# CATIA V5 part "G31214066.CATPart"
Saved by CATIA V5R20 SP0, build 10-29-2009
Part number: G31214066
Revision: 3
Definition: design
Nomenclature: G31214066
Source: made
Description: NOT SPECIFIED
Bounding box of the stored display mesh (mm): x -6 to 66, y -12.31 to 12.31, z -12.5 to 12.5
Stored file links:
  C:\Users\Raffaele\Desktop\3D X SITO CF\BOLEX\23-BUSH REF 312\G31214066.CATPart

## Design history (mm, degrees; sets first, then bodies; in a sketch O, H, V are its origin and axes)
Body1 "MANIFOLD_SOLID_BREP #14731" (main body)
  Solid1: solid without history
Body2 "MANIFOLD_SOLID_BREP #14874"
  Solid2: solid without history
Body3 "MANIFOLD_SOLID_BREP #15017"
  Solid3: solid without history
Body4 "MANIFOLD_SOLID_BREP #15160"
  Solid4: solid without history
Body5 "MANIFOLD_SOLID_BREP #15303"
  Solid5: solid without history
Body6 "MANIFOLD_SOLID_BREP #15448"
  Solid6: solid without history
Body7 "MANIFOLD_SOLID_BREP #15593"
  Solid7: solid without history
Body8 "MANIFOLD_SOLID_BREP #15738"
  Solid8: solid without history
Body9 "MANIFOLD_SOLID_BREP #15883"
  Solid9: solid without history
Body10 "MANIFOLD_SOLID_BREP #16028"
  Solid10: solid without history
Body11 "MANIFOLD_SOLID_BREP #16173"
  Solid11: solid without history
Body12 "MANIFOLD_SOLID_BREP #16318"
  Solid12: solid without history
Body13 "MANIFOLD_SOLID_BREP #16463"
  Solid13: solid without history
Body14 "MANIFOLD_SOLID_BREP #16608"
  Solid14: solid without history
Body15 "MANIFOLD_SOLID_BREP #16753"
  Solid15: solid without history
Body16 "MANIFOLD_SOLID_BREP #16898"
  Solid16: solid without history
Body17 "MANIFOLD_SOLID_BREP #17043"
  Solid17: solid without history
Body18 "MANIFOLD_SOLID_BREP #17188"
  Solid18: solid without history
Body19 "MANIFOLD_SOLID_BREP #17333"
  Solid19: solid without history
Body20 "MANIFOLD_SOLID_BREP #17478"
  Solid20: solid without history
Body21 "MANIFOLD_SOLID_BREP #17623"
  Solid21: solid without history
Body22 "MANIFOLD_SOLID_BREP #17768"
  Solid22: solid without history
Body23 "MANIFOLD_SOLID_BREP #17913"
  Solid23: solid without history
Body24 "MANIFOLD_SOLID_BREP #18058"
  Solid24: solid without history
Body25 "MANIFOLD_SOLID_BREP #18203"
  Solid25: solid without history
Body26 "MANIFOLD_SOLID_BREP #18348"
  Solid26: solid without history
Body27 "MANIFOLD_SOLID_BREP #18493"
  Solid27: solid without history
Body28 "MANIFOLD_SOLID_BREP #18638"
  Solid28: solid without history
Body29 "MANIFOLD_SOLID_BREP #18783"
  Solid29: solid without history
Body30 "MANIFOLD_SOLID_BREP #18928"
  Solid30: solid without history
Body31 "MANIFOLD_SOLID_BREP #19073"
  Solid31: solid without history
Body32 "MANIFOLD_SOLID_BREP #19216"
  Solid32: solid without history
Body33 "MANIFOLD_SOLID_BREP #19359"
  Solid33: solid without history
Body34 "MANIFOLD_SOLID_BREP #19504"
  Solid34: solid without history
Body35 "MANIFOLD_SOLID_BREP #19649"
  Solid35: solid without history
Body36 "MANIFOLD_SOLID_BREP #19794"
  Solid36: solid without history
Body37 "MANIFOLD_SOLID_BREP #19939"
  Solid37: solid without history
Body38 "MANIFOLD_SOLID_BREP #20084"
  Solid38: solid without history
Body39 "MANIFOLD_SOLID_BREP #20229"
  Solid39: solid without history
Body40 "MANIFOLD_SOLID_BREP #20374"
  Solid40: solid without history
Body41 "MANIFOLD_SOLID_BREP #20519"
  Solid41: solid without history
Body42 "MANIFOLD_SOLID_BREP #20664"
  Solid42: solid without history
Body43 "MANIFOLD_SOLID_BREP #20809"
  Solid43: solid without history
Body44 "MANIFOLD_SOLID_BREP #20954"
  Solid44: solid without history
Body45 "MANIFOLD_SOLID_BREP #21099"
  Solid45: solid without history
Body46 "MANIFOLD_SOLID_BREP #21244"
  Solid46: solid without history
Body47 "MANIFOLD_SOLID_BREP #21389"
  Solid47: solid without history
Body48 "MANIFOLD_SOLID_BREP #21534"
  Solid48: solid without history
Body49 "MANIFOLD_SOLID_BREP #21679"
  Solid49: solid without history
Body50 "MANIFOLD_SOLID_BREP #21824"
  Solid50: solid without history
Body51 "MANIFOLD_SOLID_BREP #21969"
  Solid51: solid without history
Body52 "MANIFOLD_SOLID_BREP #22114"
  Solid52: solid without history
Body53 "MANIFOLD_SOLID_BREP #22259"
  Solid53: solid without history
Body54 "MANIFOLD_SOLID_BREP #22404"
  Solid54: solid without history
Body55 "MANIFOLD_SOLID_BREP #22549"
  Solid55: solid without history
Body56 "MANIFOLD_SOLID_BREP #22692"
  Solid56: solid without history
Body57 "MANIFOLD_SOLID_BREP #22835"
  Solid57: solid without history
Body58 "MANIFOLD_SOLID_BREP #22980"
  Solid58: solid without history
Body59 "MANIFOLD_SOLID_BREP #23125"
  Solid59: solid without history
Body60 "MANIFOLD_SOLID_BREP #23270"
  Solid60: solid without history
Body61 "MANIFOLD_SOLID_BREP #23415"
  Solid61: solid without history
Body62 "MANIFOLD_SOLID_BREP #23560"
  Solid62: solid without history
Body63 "MANIFOLD_SOLID_BREP #23705"
  Solid63: solid without history
Body64 "MANIFOLD_SOLID_BREP #23848"
  Solid64: solid without history
Body65 "MANIFOLD_SOLID_BREP #23991"
  Solid65: solid without history
Body66 "MANIFOLD_SOLID_BREP #24136"
  Solid66: solid without history
Body67 "MANIFOLD_SOLID_BREP #24281"
  Solid67: solid without history
Body68 "MANIFOLD_SOLID_BREP #24426"
  Solid68: solid without history
Body69 "MANIFOLD_SOLID_BREP #24571"
  Solid69: solid without history
Body70 "MANIFOLD_SOLID_BREP #24716"
  Solid70: solid without history
Body71 "MANIFOLD_SOLID_BREP #24861"
  Solid71: solid without history
Body72 "MANIFOLD_SOLID_BREP #25006"
  Solid72: solid without history
Body73 "MANIFOLD_SOLID_BREP #25151"
  Solid73: solid without history
Body74 "MANIFOLD_SOLID_BREP #25296"
  Solid74: solid without history
Body75 "MANIFOLD_SOLID_BREP #25441"
  Solid75: solid without history
Body76 "MANIFOLD_SOLID_BREP #25586"
  Solid76: solid without history
Body77 "MANIFOLD_SOLID_BREP #25731"
  Solid77: solid without history
Body78 "MANIFOLD_SOLID_BREP #25876"
  Solid78: solid without history
Body79 "MANIFOLD_SOLID_BREP #26021"
  Solid79: solid without history
Body80 "MANIFOLD_SOLID_BREP #26166"
  Solid80: solid without history
Body81 "MANIFOLD_SOLID_BREP #26311"
  Solid81: solid without history
Body82 "MANIFOLD_SOLID_BREP #26456"
  Solid82: solid without history
Body83 "MANIFOLD_SOLID_BREP #26601"
  Solid83: solid without history
Body84 "MANIFOLD_SOLID_BREP #26746"
  Solid84: solid without history
Body85 "MANIFOLD_SOLID_BREP #26891"
  Solid85: solid without history
Body86 "MANIFOLD_SOLID_BREP #27036"
  Solid86: solid without history
Body87 "MANIFOLD_SOLID_BREP #27181"
  Solid87: solid without history
Body88 "MANIFOLD_SOLID_BREP #27324"
  Solid88: solid without history
Body89 "MANIFOLD_SOLID_BREP #27467"
  Solid89: solid without history
Body90 "MANIFOLD_SOLID_BREP #27612"
  Solid90: solid without history
Body91 "MANIFOLD_SOLID_BREP #27757"
  Solid91: solid without history
Body92 "MANIFOLD_SOLID_BREP #27902"
  Solid92: solid without history
Body93 "MANIFOLD_SOLID_BREP #28047"
  Solid93: solid without history
Body94 "MANIFOLD_SOLID_BREP #28192"
  Solid94: solid without history
Body95 "MANIFOLD_SOLID_BREP #28337"
  Solid95: solid without history
Body96 "MANIFOLD_SOLID_BREP #28480"
  Solid96: solid without history
Body97 "MANIFOLD_SOLID_BREP #28623"
  Solid97: solid without history
Body98 "MANIFOLD_SOLID_BREP #28768"
  Solid98: solid without history
Body99 "MANIFOLD_SOLID_BREP #28913"
  Solid99: solid without history
Body100 "MANIFOLD_SOLID_BREP #29058"
  Solid100: solid without history
Body101 "MANIFOLD_SOLID_BREP #29203"
  Solid101: solid without history
Body102 "MANIFOLD_SOLID_BREP #29348"
  Solid102: solid without history
Body103 "MANIFOLD_SOLID_BREP #29493"
  Solid103: solid without history
Body104 "MANIFOLD_SOLID_BREP #29638"
  Solid104: solid without history
Body105 "MANIFOLD_SOLID_BREP #29783"
  Solid105: solid without history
